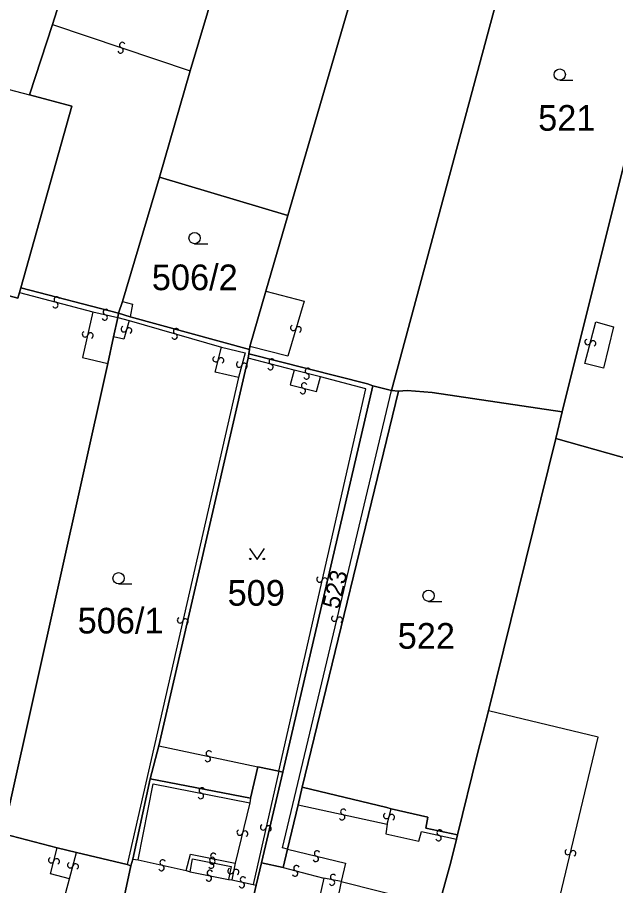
# Model space of a CAD drawing. Extents: x -600309 to -598967, y -1161267 to -1160292.
# Drawn here: x -599939.3 to -599899.7, y -1161134.8 to -1161077.3 of the extents above; entities that cross this region are included whole.
import ezdxf

# ---------------------------------------------------------------- set-up
doc = ezdxf.new("R2010")
doc.units = 0
for name, color, linetype in [('Level 1', 7, 'Continuous'), ('Level 13', 7, 'Continuous'), ('Level 3', 7, 'Continuous'), ('Level 4', 7, 'Continuous'), ('Level 5', 7, 'Continuous'), ('Level 60', 7, 'Continuous')]:
    doc.layers.add(name, color=color, linetype=linetype)

msp = doc.modelspace()

# ---------------------------------------------------------------- linework, layer by layer
at = {"layer": 'Level 1'}
for points in [[(-599914.08, -1161034.68), (-599927.85, -1161080.81)], [(-599905.93, -1161037.31), (-599921.39, -1161090.4)], [(-599906.31, -1161071.52), (-599914.53, -1161101.98)], [(-599895.94, -1161074.2), (-599903.23, -1161103.39)], [(-599936.1, -1161074.93), (-599936.97, -1161077.75)], [(-599936.97, -1161077.75), (-599938.49, -1161082.41)], [(-599927.85, -1161080.81), (-599929.9, -1161087.85)], [(-599938.49, -1161082.41), (-599935.69, -1161083.15), (-599939.08, -1161095.18)], [(-599929.9, -1161087.85), (-599932.34, -1161096.08)], [(-599921.39, -1161090.4), (-599929.9, -1161087.85)], [(-599921.39, -1161090.4), (-599922.86, -1161095.4)], [(-599939.17, -1161095.5), (-599939.28, -1161095.87), (-599942.59, -1161094.98), (-599943.75, -1161100.36)], [(-599939.08, -1161095.18), (-599939.17, -1161095.5)], [(-599939.08, -1161095.18), (-599932.61, -1161096.87)], [(-599922.86, -1161095.4), (-599923.9, -1161099.08)], [(-599932.34, -1161096.08), (-599932.61, -1161096.87)], [(-599932.61, -1161096.87), (-599932.66, -1161097.15)], [(-599932.61, -1161096.87), (-599931.83, -1161097.11)], [(-599932.66, -1161097.15), (-599932.94, -1161098.44)], [(-599931.83, -1161097.11), (-599923.94, -1161099.26)], [(-599932.94, -1161098.44), (-599933.31, -1161100.19)], [(-599923.94, -1161099.26), (-599923.97, -1161099.56)], [(-599923.9, -1161099.08), (-599923.94, -1161099.26)], [(-599924.02, -1161099.85), (-599929.94, -1161125.52)], [(-599923.97, -1161099.56), (-599924.02, -1161099.85)], [(-599923.97, -1161099.56), (-599916.12, -1161101.55), (-599915.77, -1161101.68)], [(-599933.31, -1161100.19), (-599939.84, -1161129.57)], [(-599915.77, -1161101.68), (-599921.73, -1161127.26)], [(-599920.45, -1161128.25), (-599914.07, -1161102.03)], [(-599914.53, -1161101.98), (-599915.77, -1161101.68)], [(-599914.07, -1161102.03), (-599914.53, -1161101.98)], [(-599903.23, -1161103.39), (-599911.83, -1161102.11), (-599913.49, -1161101.99), (-599914.07, -1161102.03)], [(-599903.23, -1161103.39), (-599903.65, -1161105.17)], [(-599908.11, -1161123.2), (-599903.65, -1161105.17)], [(-599903.65, -1161105.17), (-599887.6, -1161109.7)], [(-599908.11, -1161123.2), (-599908.86, -1161126.11), (-599910.16, -1161131.42)], [(-599929.94, -1161125.52), (-599930.5, -1161127.7)], [(-599923.86, -1161128.98), (-599923.39, -1161126.91)], [(-599923.39, -1161126.91), (-599922, -1161127.2)], [(-599921.73, -1161127.26), (-599923.13, -1161133.27)], [(-599922, -1161127.2), (-599921.73, -1161127.26)], [(-599930.5, -1161127.7), (-599931.65, -1161133.02)], [(-599930.5, -1161127.7), (-599923.86, -1161128.98)], [(-599920.45, -1161128.25), (-599920.7, -1161129.42)], [(-599914.56, -1161129.69), (-599914.84, -1161129.61), (-599920.45, -1161128.25)], [(-599920.7, -1161129.42), (-599921.41, -1161132.37)], [(-599910.16, -1161131.42), (-599912.26, -1161130.98), (-599912.12, -1161130.24), (-599914.56, -1161129.69)], [(-599936.67, -1161132.28), (-599940.21, -1161131.34)], [(-599910.16, -1161131.42), (-599910.23, -1161131.71)], [(-599911.39, -1161136.1), (-599910.6, -1161133.23), (-599910.23, -1161131.71)], [(-599935.38, -1161132.59), (-599936.67, -1161132.28)], [(-599932.04, -1161133.38), (-599935.38, -1161132.59)], [(-599921.41, -1161132.37), (-599921.71, -1161133.58)], [(-599931.65, -1161133.02), (-599931.8, -1161133.46)], [(-599931.8, -1161133.46), (-599935.38, -1161150.31)], [(-599931.8, -1161133.46), (-599932.04, -1161133.38)], [(-599923.13, -1161133.27), (-599923.48, -1161134.76)], [(-599921.71, -1161133.58), (-599923.13, -1161133.27)], [(-599923.48, -1161134.76), (-599927.51, -1161152.42)]]:
    msp.add_lwpolyline(points, dxfattribs=at)
at = {"layer": 'Level 13'}
for centre, start, end in [((-599932.35, -1161079.106), 18.82478, 250.92277), ((-599932.469, -1161079.454), 198.61032, 71.20032), ((-599936.691, -1161095.962), 22.64654, 254.74454), ((-599936.788, -1161096.318), 202.43209, 75.02209), ((-599933.521, -1161097.149), 204.44465, 77.03465), ((-599933.438, -1161096.79), 24.6591, 256.7571), ((-599934.819, -1161098.258), 114.32949, 346.91949), ((-599934.461, -1161098.343), 294.54395, 166.64195), ((-599932.257, -1161097.921), 111.94195, 344.53195), ((-599931.902, -1161098.02), 292.15641, 164.2544), ((-599928.787, -1161098.053), 21.18075, 253.27874), ((-599921.036, -1161097.837), 110.77726, 343.36726), ((-599920.684, -1161097.944), 290.99172, 163.08971), ((-599928.892, -1161098.407), 200.96629, 73.55629), ((-599901.538, -1161098.77), 112.22268, 344.32068), ((-599901.183, -1161098.869), 292.00823, 164.59823), ((-599926.168, -1161099.903), 113.17418, 345.27218), ((-599925.812, -1161099.996), 292.95973, 165.54973), ((-599922.453, -1161100.072), 22.59112, 255.18112), ((-599924.617, -1161100.261), 111.96303, 344.55303), ((-599924.262, -1161100.36), 292.17749, 164.27548), ((-599922.548, -1161100.428), 202.80558, 74.90358), ((-599920.158, -1161101.048), 202.87257, 74.97056), ((-599920.063, -1161100.692), 22.65811, 255.24811), ((-599920.312, -1161101.662), 22.87257, 254.97056), ((-599920.407, -1161102.018), 202.65811, 75.24811), ((-599919.299, -1161114.497), 114.55673, 346.65473), ((-599918.941, -1161114.582), 294.34227, 166.93228), ((-599928.529, -1161117.208), 114.27267, 346.86267), ((-599928.171, -1161117.293), 294.48712, 166.58512), ((-599918.319, -1161117.086), 113.97001, 346.06801), ((-599917.961, -1161117.173), 293.75556, 166.34556), ((-599926.699, -1161126.39), 205.17707, 77.76707), ((-599926.62, -1161126.03), 25.39153, 257.48953), ((-599927.083, -1161128.479), 26.21808, 258.31607), ((-599927.156, -1161128.84), 206.00362, 78.59362), ((-599917.719, -1161129.89), 24.92635, 257.02435), ((-599917.8, -1161130.25), 204.71189, 77.30189), ((-599914.869, -1161130.155), 113.72982, 345.82782), ((-599914.511, -1161130.244), 293.51536, 166.10536), ((-599923.029, -1161130.919), 114.40348, 346.99348), ((-599922.67, -1161131.002), 294.61794, 166.71594), ((-599924.579, -1161131.256), 113.55991, 346.14991), ((-599924.221, -1161131.345), 293.77437, 165.87236), ((-599911.421, -1161131.629), 204.47199, 77.06199), ((-599911.338, -1161131.27), 24.68645, 256.78444), ((-599926.321, -1161132.82), 25.83811, 257.93611), ((-599919.455, -1161132.651), 23.86568, 255.96368), ((-599902.859, -1161132.555), 113.84868, 345.94667), ((-599902.501, -1161132.644), 293.63422, 166.22422), ((-599937.059, -1161133.094), 113.33649, 345.43449), ((-599936.702, -1161133.185), 293.12203, 165.71203), ((-599935.798, -1161133.421), 112.33948, 344.43747), ((-599929.679, -1161133.25), 24.99616, 257.09415), ((-599926.392, -1161133.089), 26.0628, 258.1608), ((-599926.398, -1161133.18), 205.62366, 78.21366), ((-599919.544, -1161133.009), 203.65123, 76.24123), ((-599935.442, -1161133.519), 292.12502, 164.71502), ((-599929.76, -1161133.61), 204.7817, 77.3717), ((-599926.552, -1161133.939), 26.15028, 258.24827), ((-599926.467, -1161133.45), 205.84834, 78.43834), ((-599925.181, -1161133.815), 116.35005, 348.94005), ((-599924.819, -1161133.886), 296.5645, 168.6625), ((-599920.917, -1161133.978), 202.48188, 75.07188), ((-599920.822, -1161133.622), 22.69634, 254.79434), ((-599926.627, -1161134.3), 205.93582, 78.52582), ((-599924.358, -1161134.38), 24.88727, 256.98526), ((-599918.468, -1161134.58), 205.96618, 78.06418), ((-599918.393, -1161134.22), 25.75173, 258.34173), ((-599924.441, -1161134.74), 204.67281, 77.26281)]:
    msp.add_arc(centre, 0.184, start, end, dxfattribs=at)
at = {"layer": 'Level 3'}
for points in [[(-599936.97, -1161077.75), (-599927.85, -1161080.81)], [(-599948.37, -1161079.79), (-599947.8, -1161079.95), (-599947.98, -1161080.55), (-599943.63, -1161081.67), (-599943.49, -1161081.09), (-599938.49, -1161082.41)], [(-599939.17, -1161095.5), (-599934.3, -1161096.78)], [(-599922.86, -1161095.4), (-599920.32, -1161096.07), (-599921.39, -1161099.71), (-599923.9, -1161099.08)], [(-599932.34, -1161096.08), (-599931.67, -1161096.27), (-599931.83, -1161097.11)], [(-599934.3, -1161096.78), (-599934.99, -1161099.81), (-599933.31, -1161100.19)], [(-599934.3, -1161096.78), (-599932.66, -1161097.15)], [(-599931.91, -1161097.34), (-599932.25, -1161098.59), (-599932.94, -1161098.44)], [(-599932.66, -1161097.15), (-599931.91, -1161097.34)], [(-599931.91, -1161097.34), (-599925.78, -1161099.12)], [(-599901.74, -1161100.2), (-599900.99, -1161097.43), (-599899.82, -1161097.76), (-599900.49, -1161100.5), (-599901.74, -1161100.2)], [(-599924.66, -1161101.12), (-599926.2, -1161100.78), (-599925.78, -1161099.12)], [(-599925.78, -1161099.12), (-599924.22, -1161099.5), (-599924.66, -1161101.12)], [(-599920.98, -1161100.64), (-599924.02, -1161099.85)], [(-599920.98, -1161100.64), (-599921.23, -1161101.61), (-599919.49, -1161102.06), (-599919.24, -1161101.09)], [(-599919.24, -1161101.09), (-599920.98, -1161100.64)], [(-599924.66, -1161101.12), (-599932.04, -1161133.38)], [(-599922, -1161127.2), (-599916.24, -1161101.88), (-599919.24, -1161101.09)], [(-599921.41, -1161132.37), (-599921.75, -1161132.28), (-599914.53, -1161101.98)], [(-599895.98, -1161142.27), (-599904.52, -1161140.25), (-599900.84, -1161124.95), (-599908.11, -1161123.2)], [(-599929.94, -1161125.52), (-599923.39, -1161126.91)], [(-599922, -1161127.2), (-599923.7, -1161134.71)], [(-599931.31, -1161133.08), (-599930.31, -1161128.03), (-599923.92, -1161129.29)], [(-599923.86, -1161128.98), (-599923.92, -1161129.29)], [(-599923.92, -1161129.29), (-599924.89, -1161133.3)], [(-599920.7, -1161129.42), (-599914.81, -1161130.72)], [(-599914.81, -1161130.72), (-599914.56, -1161129.69)], [(-599914.81, -1161130.72), (-599914.91, -1161131.36), (-599912.73, -1161131.84), (-599912.54, -1161131.19), (-599910.23, -1161131.71)], [(-599935.85, -1161134.34), (-599937.1, -1161134), (-599936.67, -1161132.28)], [(-599935.85, -1161134.34), (-599935.38, -1161132.59)], [(-599921.41, -1161132.37), (-599917.58, -1161133.29), (-599917.86, -1161134.51)], [(-599931.65, -1161133.02), (-599931.31, -1161133.08)], [(-599931.31, -1161133.08), (-599928.12, -1161133.78)], [(-599928.12, -1161133.78), (-599927.83, -1161132.7), (-599924.89, -1161133.3)], [(-599927.85, -1161133.87), (-599927.7, -1161133.01), (-599925.15, -1161133.52), (-599925.33, -1161134.37)], [(-599928.12, -1161133.78), (-599927.85, -1161133.87)], [(-599924.89, -1161133.3), (-599925.1, -1161134.4)], [(-599921.71, -1161133.58), (-599920.03, -1161134.02), (-599919, -1161134.28)], [(-599936.9, -1161138.28), (-599935.85, -1161134.34)], [(-599927.85, -1161133.87), (-599925.33, -1161134.37)], [(-599925.33, -1161134.37), (-599925.1, -1161134.4)], [(-599925.1, -1161134.4), (-599923.7, -1161134.71)], [(-599919, -1161134.28), (-599919.32, -1161135.66), (-599919.95, -1161138.22)], [(-599917.86, -1161134.51), (-599919, -1161134.28)], [(-599923.7, -1161134.71), (-599923.48, -1161134.76)], [(-599917.86, -1161134.51), (-599918.37, -1161137)], [(-599917.86, -1161134.51), (-599912.7, -1161135.82)]]:
    msp.add_lwpolyline(points, dxfattribs=at)
at = {"layer": 'Level 5'}
for p, q in [((-599903.39, -1161081.44), (-599902.515, -1161081.44)), ((-599927.57, -1161092.26), (-599926.695, -1161092.26)), ((-599932.6, -1161114.8), (-599931.725, -1161114.8)), ((-599912.07, -1161115.95), (-599911.195, -1161115.95))]:
    msp.add_line(p, q, dxfattribs=at)
msp.add_lwpolyline([(-599923.931, -1161112.44), (-599923.43, -1161113.19), (-599922.93, -1161112.44)], dxfattribs=at)
for centre, radius in [((-599903.39, -1161081.065), 0.375), ((-599927.57, -1161091.885), 0.375), ((-599923.88, -1161113.14), 0.05), ((-599922.981, -1161113.14), 0.05), ((-599932.6, -1161114.425), 0.375), ((-599912.07, -1161115.575), 0.375)]:
    msp.add_circle(centre, radius, dxfattribs=at)
at = {"layer": 'Level 60'}
for points in [[(-599936.1, -1161074.93), (-599922.3, -1161032.03), (-599914.08, -1161034.68), (-599927.85, -1161080.81), (-599929.9, -1161087.85), (-599932.34, -1161096.08), (-599932.61, -1161096.87), (-599939.08, -1161095.18), (-599935.69, -1161083.15), (-599938.49, -1161082.41), (-599936.97, -1161077.75)], [(-599927.85, -1161080.81), (-599914.08, -1161034.68), (-599905.93, -1161037.31), (-599921.39, -1161090.4), (-599929.9, -1161087.85)], [(-599921.39, -1161090.4), (-599905.93, -1161037.31), (-599897.85, -1161039.96), (-599903.12, -1161059.71), (-599906.31, -1161071.52), (-599914.53, -1161101.98), (-599915.77, -1161101.68), (-599916.12, -1161101.55), (-599923.97, -1161099.56), (-599923.94, -1161099.26), (-599923.9, -1161099.08), (-599922.86, -1161095.4)], [(-599903.65, -1161105.17), (-599903.23, -1161103.39), (-599895.94, -1161074.2), (-599892.84, -1161061.79), (-599867.28, -1161067.4), (-599877.21, -1161112.63), (-599887.6, -1161109.7)], [(-599948.08, -1161078.93), (-599945.61, -1161071.42), (-599936.1, -1161074.93), (-599936.97, -1161077.75), (-599938.49, -1161082.41), (-599935.69, -1161083.15), (-599939.08, -1161095.18), (-599939.17, -1161095.5), (-599939.28, -1161095.87), (-599942.59, -1161094.98), (-599943.75, -1161100.36), (-599953.71, -1161097.86), (-599953.98, -1161097.8), (-599953.21, -1161094.85), (-599952.69, -1161092.5), (-599948.37, -1161079.79)], [(-599903.23, -1161103.39), (-599911.83, -1161102.11), (-599913.49, -1161101.99), (-599914.07, -1161102.03), (-599914.53, -1161101.98), (-599906.31, -1161071.52), (-599895.94, -1161074.2)], [(-599932.34, -1161096.08), (-599929.9, -1161087.85), (-599921.39, -1161090.4), (-599922.86, -1161095.4), (-599923.9, -1161099.08), (-599923.94, -1161099.26), (-599931.83, -1161097.11), (-599932.61, -1161096.87)], [(-599945.7, -1161109.72), (-599943.75, -1161100.36), (-599942.59, -1161094.98), (-599939.28, -1161095.87), (-599939.17, -1161095.5), (-599939.08, -1161095.18), (-599932.61, -1161096.87), (-599932.66, -1161097.15), (-599932.94, -1161098.44), (-599933.31, -1161100.19), (-599939.84, -1161129.57), (-599946.52, -1161127.87), (-599949.1, -1161127.24), (-599949.34, -1161127.15), (-599948.24, -1161121.79)], [(-599939.96, -1161129.87), (-599939.84, -1161129.57), (-599933.31, -1161100.19), (-599932.94, -1161098.44), (-599932.66, -1161097.15), (-599932.61, -1161096.87), (-599931.83, -1161097.11), (-599923.94, -1161099.26), (-599923.97, -1161099.56), (-599924.02, -1161099.85), (-599929.94, -1161125.52), (-599930.5, -1161127.7), (-599931.65, -1161133.02), (-599931.8, -1161133.46), (-599932.04, -1161133.38), (-599935.38, -1161132.59), (-599936.67, -1161132.28), (-599940.21, -1161131.34)], [(-599924.02, -1161099.85), (-599923.97, -1161099.56), (-599916.12, -1161101.55), (-599915.77, -1161101.68), (-599921.73, -1161127.26), (-599922, -1161127.2), (-599923.39, -1161126.91), (-599923.86, -1161128.98), (-599930.5, -1161127.7), (-599929.94, -1161125.52)], [(-599923.13, -1161133.27), (-599921.73, -1161127.26), (-599915.77, -1161101.68), (-599914.53, -1161101.98), (-599914.07, -1161102.03), (-599920.45, -1161128.25), (-599920.7, -1161129.42), (-599921.41, -1161132.37), (-599921.71, -1161133.58)], [(-599911.83, -1161102.11), (-599903.23, -1161103.39), (-599903.65, -1161105.17), (-599908.11, -1161123.2), (-599908.86, -1161126.11), (-599910.16, -1161131.42), (-599912.26, -1161130.98), (-599912.12, -1161130.24), (-599914.56, -1161129.69), (-599914.84, -1161129.61), (-599920.45, -1161128.25), (-599914.07, -1161102.03), (-599913.49, -1161101.99)], [(-599931.65, -1161133.02), (-599930.5, -1161127.7), (-599923.86, -1161128.98), (-599923.39, -1161126.91), (-599922, -1161127.2), (-599921.73, -1161127.26), (-599923.13, -1161133.27), (-599923.48, -1161134.76), (-599927.51, -1161152.42), (-599935.38, -1161150.31), (-599931.8, -1161133.46)], [(-599923.48, -1161134.76), (-599923.13, -1161133.27), (-599921.71, -1161133.58), (-599921.41, -1161132.37), (-599920.7, -1161129.42), (-599920.45, -1161128.25), (-599914.84, -1161129.61), (-599914.56, -1161129.69), (-599912.12, -1161130.24), (-599912.26, -1161130.98), (-599910.16, -1161131.42), (-599910.23, -1161131.71), (-599910.6, -1161133.23), (-599911.39, -1161136.1), (-599911.93, -1161138.5), (-599913.21, -1161143.41), (-599913.35, -1161144.14), (-599916.19, -1161155.41), (-599927.51, -1161152.42)], [(-599941.27, -1161135.74), (-599940.21, -1161131.34), (-599936.67, -1161132.28), (-599935.38, -1161132.59), (-599932.04, -1161133.38), (-599931.8, -1161133.46), (-599935.38, -1161150.31), (-599944.17, -1161148.1), (-599942.26, -1161139.88), (-599941.55, -1161137.12)]]:
    msp.add_lwpolyline(points, close=True, dxfattribs=at)
msp.add_lwpolyline([(-599899.56, -1161160.29), (-599900.68, -1161160.69), (-599903.77, -1161159.99), (-599904.8, -1161158.92), (-599905.57, -1161158.12), (-599916.19, -1161155.41), (-599913.35, -1161144.14), (-599913.21, -1161143.41), (-599911.93, -1161138.5), (-599911.39, -1161136.1), (-599910.6, -1161133.23), (-599910.23, -1161131.71), (-599910.16, -1161131.42), (-599908.86, -1161126.11), (-599908.11, -1161123.2), (-599903.65, -1161105.17), (-599887.6, -1161109.7)], dxfattribs=at)

# ---------------------------------------------------------------- texts
at = {"layer": 'Level 4'}
for s, p in [('521', (-599904.82, -1161084.78)), ('506/2', (-599930.4, -1161095.34)), ('509', (-599925.38, -1161116.24)), ('506/1', (-599935.31, -1161118.08)), ('522', (-599914.12, -1161119.09))]:
    msp.add_text(s, height=1.7, dxfattribs=at).set_placement(p)
msp.add_text('523', height=1.14, rotation=76.5, dxfattribs=at).set_placement((-599918.02, -1161116.52))

doc.saveas('drawing.dxf')
